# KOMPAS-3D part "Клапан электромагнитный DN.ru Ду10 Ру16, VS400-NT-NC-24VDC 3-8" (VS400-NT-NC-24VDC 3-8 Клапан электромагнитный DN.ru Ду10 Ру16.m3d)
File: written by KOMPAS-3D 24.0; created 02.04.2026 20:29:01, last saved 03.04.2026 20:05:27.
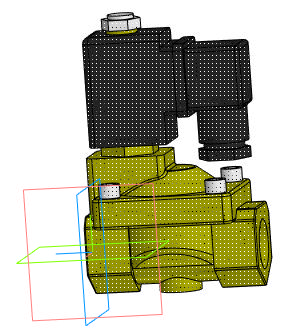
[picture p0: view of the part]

Document properties: Автор: artio; Полное имя файла: C:\Users\artio\OneDrive\Рабочий стол\Клапан электромагнитный DN.ru\VS400-NT-NC\VS400-NT-NC-24VDC 3-8 Клапан электромагнитный DN.ru Ду10 Ру16.m3d

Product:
- Body: Тело 1  | qty 1
    Масса: 1.030062
- Part/product: Клапан электромагнитный DN.ru Ду10 Ру16  | designation VS400-NT-NC-24VDC 3-8
    Масса: 0.797
    Раздел спецификации: Прочие изделия
    Примечание: D130-04725
    additional columns: ef56311e-7521-43dc-8291-0e6108b3d81d; VS400-ET-NC-220VAC 3-8; artio; c; Шероховатость не задана; Да

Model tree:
1. Операция без истории:1

Expressions: VS400-NT-NC-24VDC 3-8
